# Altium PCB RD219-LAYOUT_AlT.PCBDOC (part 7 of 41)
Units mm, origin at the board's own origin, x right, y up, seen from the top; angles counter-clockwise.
Board outline 209.75 x 159.97 mm, 2 copper layers (TOP, BOTTOM), stack 0 mm thick; 398 components, 199 nets, 1469 pads, 0 vias.
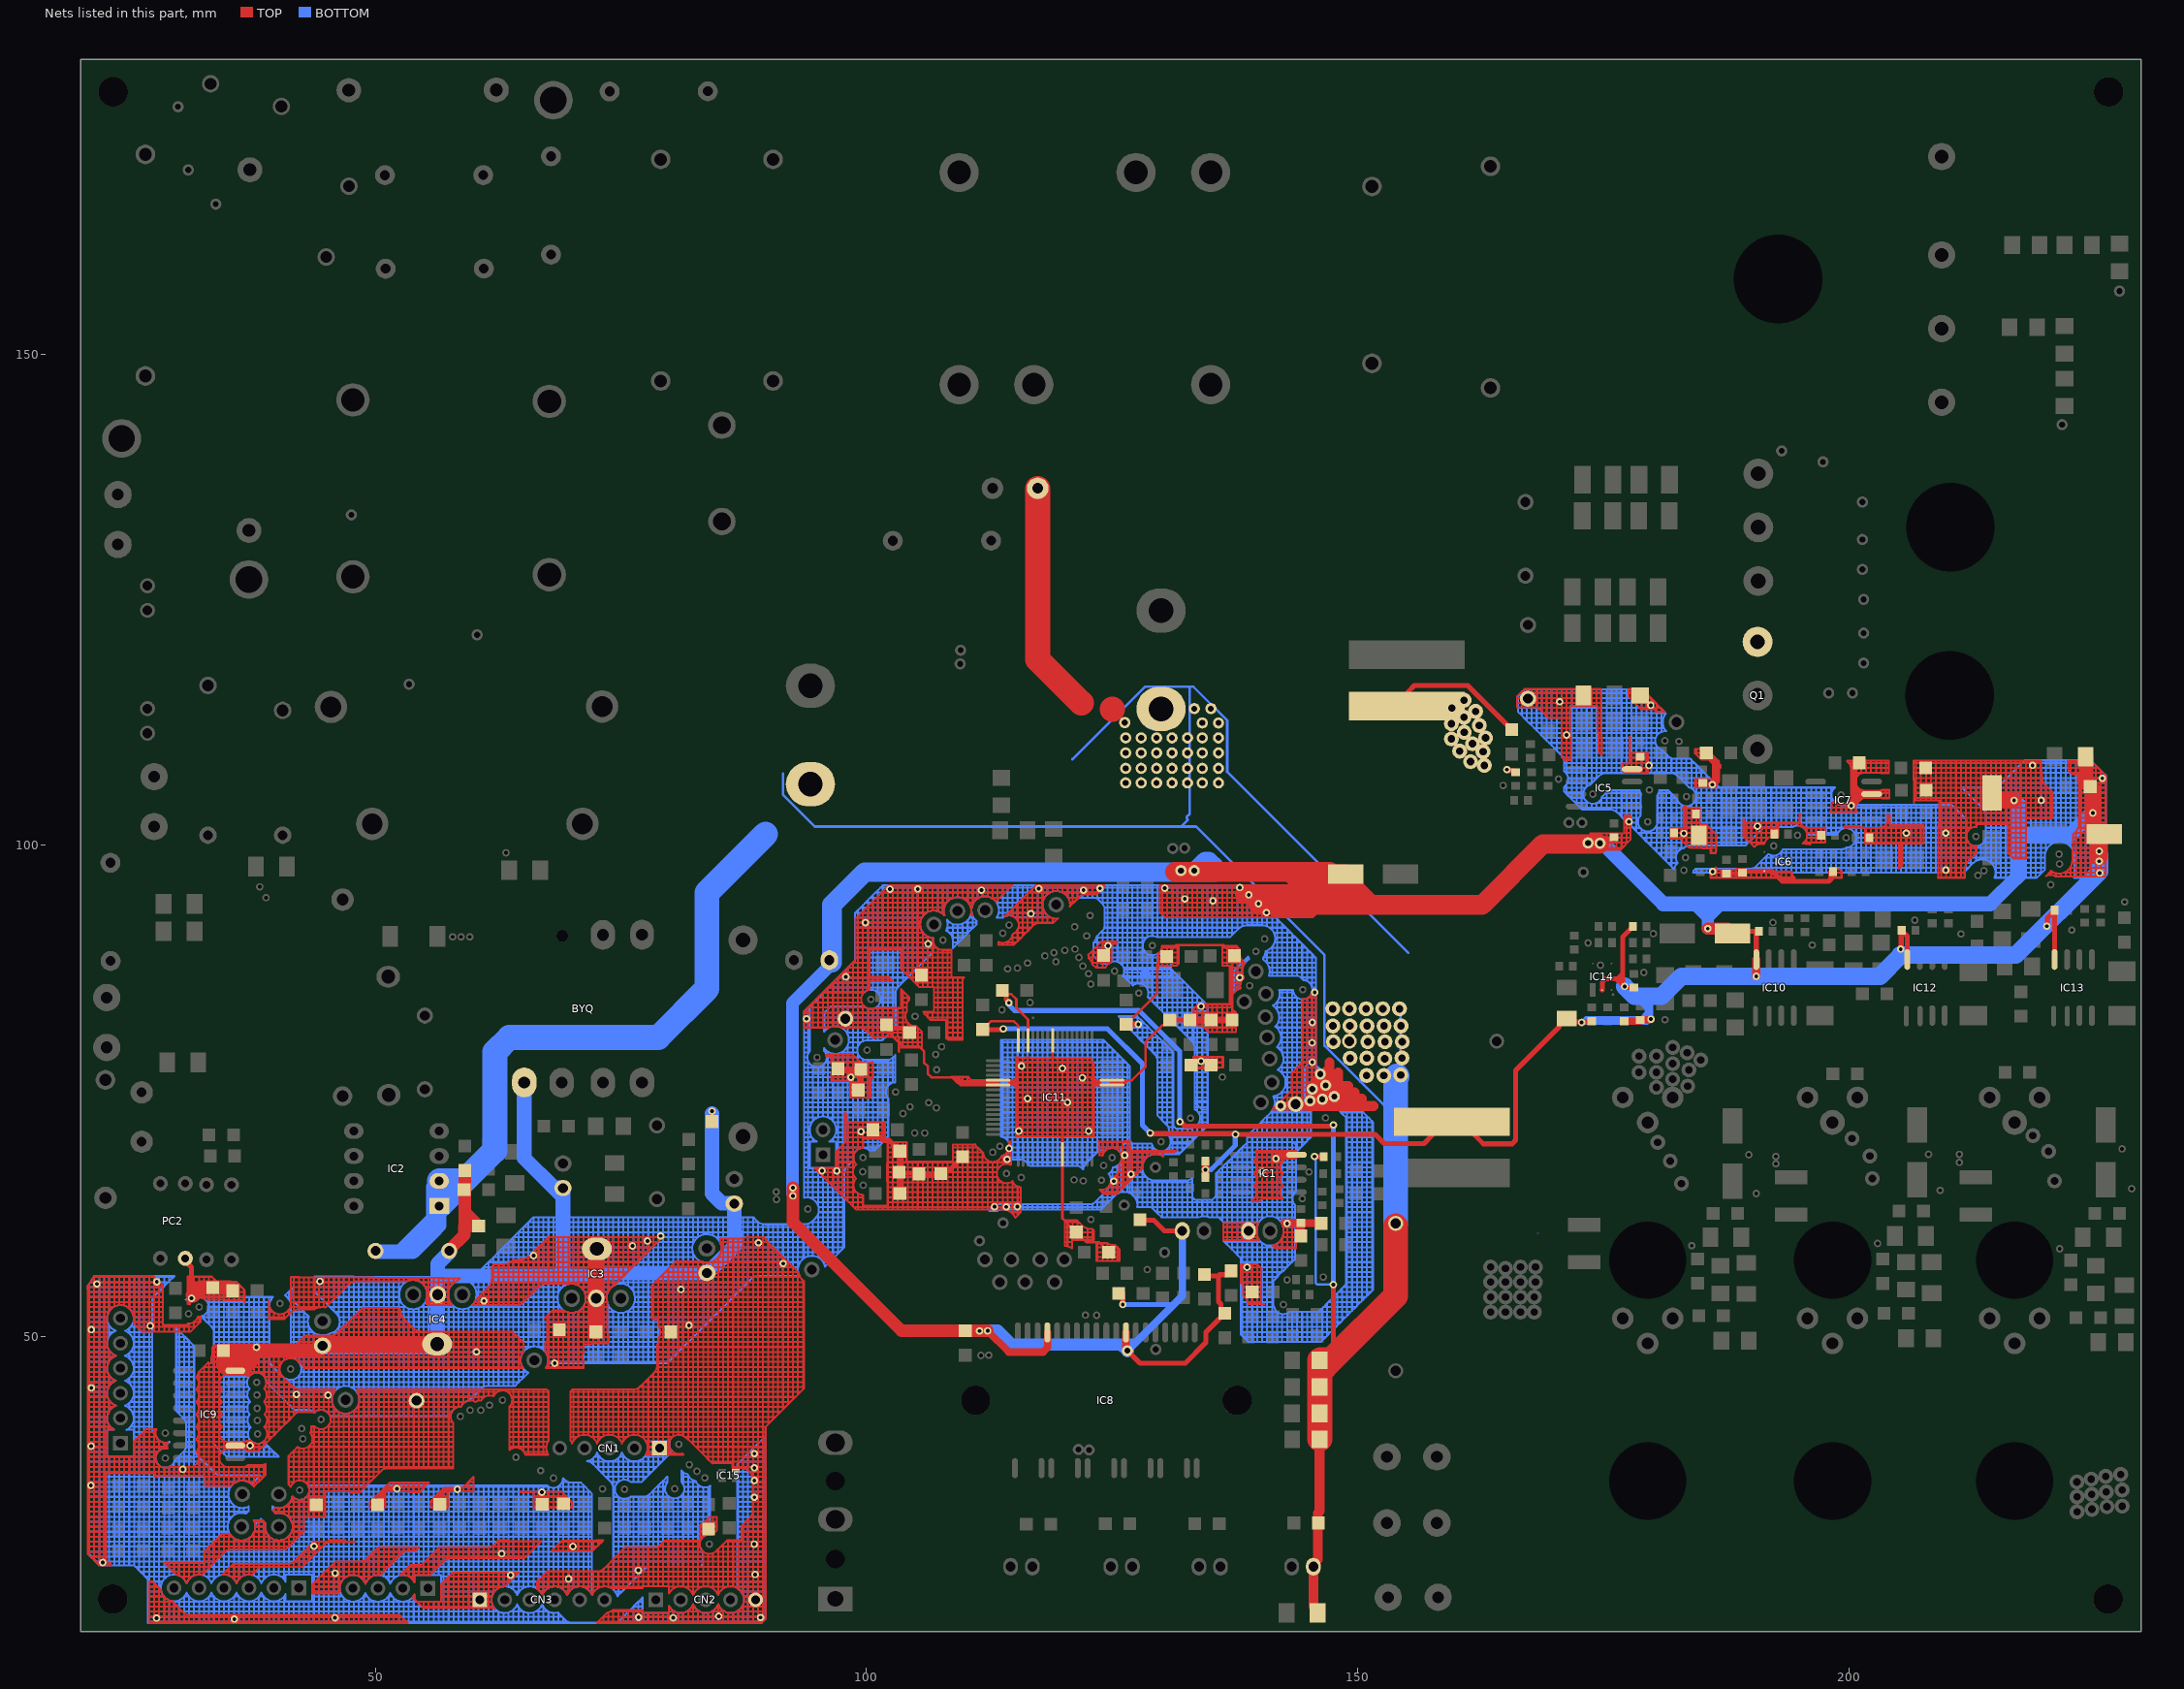
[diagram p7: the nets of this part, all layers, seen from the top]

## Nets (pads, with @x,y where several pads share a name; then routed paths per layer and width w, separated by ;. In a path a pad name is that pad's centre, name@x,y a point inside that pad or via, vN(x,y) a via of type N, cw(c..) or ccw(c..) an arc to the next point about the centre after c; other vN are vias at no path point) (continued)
GND: (continued)
  TOP w0.203: 49.845,46.838 49.845,46.924 ; 49.845,46.838 50.353,46.838 ; 49.845,46.924 49.845,47.432 ; 49.845,46.924 50.353,46.924 ; 49.845,47.432 49.845,47.94 ; 49.845,47.432 50.353,47.432 ; 49.845,47.94 49.845,48.448 ; 49.845,47.94 50.353,47.94 ; 49.845,48.448 49.845,48.956 ; 49.845,48.448 50.353,48.448 ; 49.845,48.956 49.845,49.112 49.845,49.464 ; 49.845,48.956 50.353,48.956 ; 49.845,49.464 49.845,49.972 ; 49.845,49.464 50.353,49.464 ; 49.845,49.972 49.845,50.48 ; 49.845,49.972 50.353,49.972 ; 49.845,50.48 49.845,50.988 ; 49.845,50.48 50.353,50.48 ; 49.845,50.988 49.845,51.496 ; 49.845,50.988 50.353,50.988 ; 49.845,51.496 49.845,52.004 ; 49.845,51.496 50.353,51.496 ; 49.845,52.004 49.845,52.512 ; 49.845,52.004 50.353,52.004 ; 49.845,52.512 49.845,52.938 ; 49.845,52.512 50.353,52.512 ; 49.845,52.938 50.353,52.938 ; 49.845,55.642 49.845,56.009 ; 49.845,55.642 50.353,55.642 ; 49.845,56.009 50.353,56.005 ; 49.859,28.128 50.353,28.128 ; 49.859,28.128 50.274,28.542 50.353,28.542 ; 50.008,35.748 50.353,36.093 ; 50.037,33.716 50.545,34.224 ; 50.037,33.716 50.353,33.716 ; 50.353,20.889 50.353,21.016 ; 50.353,20.889 50.861,20.889 ; 50.353,21.016 50.353,21.524 ; 50.353,21.016 50.861,21.016 ; 50.353,21.524 50.353,21.692 ; 50.353,21.524 50.861,21.524 ; 50.353,21.692 50.861,21.692 ; 50.353,25.746 50.353,26.096 ; 50.353,26.096 50.353,26.604 ; 50.353,26.096 50.847,26.096 ; 50.353,26.604 50.353,27.112 ; 50.353,26.604 50.861,26.604 ; 50.353,27.112 50.353,27.62 ; 50.353,27.112 50.861,27.112 ; 50.353,27.62 50.353,28.128 ; 50.353,27.62 50.861,27.62 ; 50.353,28.128 50.861,28.128 ; 50.353,28.128 50.353,28.542 ; 50.353,28.542 50.861,28.542 ; R74.1@50.353,32.596 R74.1@50.353,32.7 ; R74.1@50.353,32.596 R74.1@50.861,32.596 ; R74.1@50.353,32.7 R74.1@50.861,32.7 ; R74.1@50.353,32.7 50.353,33.03 R74.1@50.353,33.208 ; R74.1@50.353,33.208 50.353,33.716 ; R74.1@50.353,33.208 50.531,33.208 R74.1@50.861,33.208 ; 50.353,33.716 50.564,33.716 50.861,33.716 ; 50.353,36.093 50.353,36.256 ; 50.353,36.093 50.651,36.39 ; 50.353,36.256 50.353,36.764 ; 50.353,36.764 50.353,37.272 ; 50.353,36.764 50.861,36.764 ; 50.353,37.272 50.353,37.78 ; 50.353,37.272 50.861,37.272 ; 50.353,37.78 50.353,38.288 ; 50.353,37.78 50.861,37.78 ; 50.353,38.288 50.353,38.796 ; 50.353,38.288 50.861,38.288 ; 50.353,38.796 50.353,39.304 ; 50.353,38.796 50.861,38.796 ; 50.353,39.304 50.353,39.812 ; 50.353,39.304 50.861,39.304 ; 50.353,39.812 50.353,40.32 ; 50.353,39.812 50.861,39.812 ; 50.353,40.32 50.353,40.828 ; 50.353,40.32 50.861,40.32 ; 50.353,40.828 50.353,41.336 ; 50.353,40.828 50.861,40.828 ; 50.353,41.336 50.353,41.844 ; 50.353,41.336 50.861,41.336 ; 50.353,41.844 50.353,42.352 ; 50.353,41.844 50.861,41.844 ; 50.353,42.352 50.353,42.86 ; 50.353,42.352 50.861,42.352 ; 50.353,42.86 50.353,43.368 ; 50.353,42.86 50.861,42.86 ; 50.353,43.368 50.353,43.876 ; 50.353,43.368 50.861,43.368 ; 50.353,43.876 50.353,44.384 ; 50.353,43.876 50.861,43.876 ; 50.353,44.384 50.353,44.635 ; 50.353,44.384 50.861,44.384 ; 50.353,44.635 50.861,44.635 ; 50.353,46.838 50.353,46.924 ; 50.353,46.838 50.861,46.838 ; 50.353,46.924 50.353,47.432 ; 50.353,46.924 50.861,46.924 ; 50.353,47.432 50.353,47.94 ; 50.353,47.432 50.861,47.432 ; 50.353,47.94 50.353,48.448 ; 50.353,47.94 50.861,47.94 ; 50.353,48.448 50.353,48.956 ; 50.353,48.448 50.861,48.448 ; 50.353,48.956 50.353,49.112 50.353,49.464 ; 50.353,48.956 50.861,48.956 ; 50.353,49.464 50.353,49.972 ; 50.353,49.464 50.861,49.464 ; 50.353,49.972 50.353,50.48 ; 50.353,49.972 50.861,49.972 ; 50.353,50.48 50.353,50.988 ; 50.353,50.48 50.861,50.48 ; 50.353,50.988 50.353,51.496 ; 50.353,50.988 50.861,50.988 ; 50.353,51.496 50.353,52.004 ; 50.353,51.496 50.861,51.496 ; 50.353,52.004 50.353,52.512 ; 50.353,52.004 50.861,52.004 ; 50.353,52.512 50.353,52.938 ; 50.353,52.512 50.861,52.512 ; 50.353,52.938 50.861,52.938 ; 50.353,55.642 50.353,56.005 ; 50.353,55.642 50.861,55.642 ; 50.353,56.005 50.861,56.002 ; 50.545,34.224 50.861,34.54 ; 50.545,34.224 50.861,34.224 ; 50.651,36.39 cw(c51.166,35.875) 50.858,36.535 ; 50.651,36.39 cw(c51.166,35.875) 50.858,36.535 ; 50.847,26.096 50.861,26.11 ; 50.858,36.535 cw(c51.166,35.875) 50.861,36.537 ; 50.858,36.535 cw(c51.166,35.875) 50.861,36.537 ; 50.861,20.889 50.861,21.016 ; 50.861,20.889 51.369,20.889 ; 50.861,21.016 50.861,21.524 ; 50.861,21.016 51.369,21.016 ; 50.861,21.524 50.861,21.692 ; 50.861,21.524 51.369,21.524 ; 50.861,21.692 51.369,21.692 ; 50.861,26.11 50.861,26.604 ; 50.861,26.11 51.355,26.604 ; 50.861,26.604 50.861,27.112 ; 50.861,26.604 51.355,26.604 ; 50.861,27.112 50.861,27.62 ; 50.861,27.112 51.369,27.112 ; 50.861,27.62 50.861,28.128 ; 50.861,27.62 51.369,27.62 ; 50.861,28.128 50.861,28.542 ; 50.861,28.128 51.369,28.128 ; 50.861,28.542 51.369,28.542 ; R74.1@50.861,32.596 R74.1@50.861,32.7 ; R74.1@50.861,32.596 51.006,32.596 51.006,32.7 ; R74.1@50.861,32.7 51.006,32.7 ; R74.1@50.861,32.7 R74.1@50.861,33.208 ; R74.1@50.861,33.208 50.861,33.716 ; R74.1@50.861,33.208 51.006,33.208 ; 50.861,33.716 50.861,34.224 ; 50.861,33.716 51.006,33.716 ; 50.861,34.224 50.861,34.54 ; 50.861,34.224 51.006,34.224 ; 50.861,34.54 51.053,34.732 ; 50.861,36.537 cw(c51.166,35.875) 51.166,36.604 ; 50.861,36.537 cw(c51.166,35.875) 51.166,36.604 ; 50.861,36.537 50.861,36.764 ; 50.861,36.764 51.369,36.764 ; 50.861,36.764 50.861,37.272 ; 50.861,37.272 50.861,37.78 ; 50.861,37.272 51.369,37.272 ; 50.861,37.78 51.369,37.78 ; 50.861,37.78 50.861,38.288 ; 50.861,38.288 50.861,38.796 ; 50.861,38.288 51.369,38.288 ; 50.861,38.796 50.861,39.304 ; 50.861,38.796 51.369,38.796 ; 50.861,39.304 50.861,39.812 ; 50.861,39.304 51.369,39.304 ; 50.861,39.812 50.861,40.32 ; 50.861,39.812 51.369,39.812 ; 50.861,40.32 51.369,40.32 ; 50.861,40.32 50.861,40.828 ; 50.861,40.828 50.861,41.336 ; 50.861,40.828 51.369,40.828 ; 50.861,41.336 51.369,41.336 ; 50.861,41.336 50.861,41.844 ; 50.861,41.844 50.861,42.352 ; 50.861,41.844 51.369,41.844 ; 50.861,42.352 50.861,42.86 ; 50.861,42.352 51.369,42.352 ; 50.861,42.86 50.861,43.368 ; 50.861,42.86 51.369,42.86 ; 50.861,43.368 51.369,43.368 ; 50.861,43.368 50.861,43.876 ; 50.861,43.876 51.369,43.876 ; 50.861,43.876 50.861,44.384 ; 50.861,44.384 51.369,44.384 ; 50.861,44.384 50.861,44.635 ; 50.861,44.635 51.369,44.635 ; 50.861,46.838 50.861,46.924 ; 50.861,46.838 51.369,46.838 ; 50.861,46.924 50.861,47.432 ; 50.861,46.924 51.369,46.924 ; 50.861,47.432 50.861,47.94 ; 50.861,47.432 51.369,47.432 ; 50.861,47.94 50.861,48.448 ; 50.861,47.94 51.369,47.94 ; 50.861,48.448 50.861,48.956 ; 50.861,48.448 51.369,48.448 ; 50.861,48.956 50.861,49.112 50.861,49.464 ; 50.861,48.956 51.369,48.956 ; 50.861,49.464 50.861,49.972 ; 50.861,49.464 51.369,49.464 ; 50.861,49.972 50.861,50.48 ; 50.861,49.972 51.369,49.972 ; 50.861,50.48 50.861,50.988 ; 50.861,50.48 51.369,50.48 ; 50.861,50.988 50.861,51.496 ; 50.861,50.988 51.369,50.988 ; 50.861,51.496 50.861,52.004 ; 50.861,51.496 51.369,51.496 ; 50.861,52.004 50.861,52.512 ; 50.861,52.004 51.369,52.004 ; 50.861,52.512 50.861,52.938 ; 50.861,52.512 51.369,52.512 ; 50.861,52.938 51.369,52.938 ; 50.861,55.642 50.861,56.002 ; 50.861,55.642 51.369,55.642 ; 50.861,56.002 51.369,55.998 ; 51.006,32.7 51.006,33.208 ; 51.006,33.208 51.006,33.716 ; 51.006,33.716 51.006,34.224 ; 51.006,34.224 51.006,34.282 51.369,34.282 ; 51.053,34.732 51.369,34.732 ; 51.053,34.732 51.369,35.048 ; 51.166,36.604 51.369,36.604 ; 51.355,26.604 51.369,26.618 ; 51.369,20.889 51.369,21.016 ; 51.369,20.889 51.877,20.889 ; 51.369,21.016 51.369,21.524 ; 51.369,21.016 51.877,21.016 ; 51.369,21.524 51.369,21.692 ; 51.369,21.524 51.877,21.524 ; 51.369,21.692 51.877,21.692 ; 51.369,26.618 51.863,27.112 ; 51.369,26.618 51.369,27.112 ; 51.369,27.112 51.863,27.112 ; 51.369,27.112 51.369,27.62 ; 51.369,27.62 51.369,28.128 ; 51.369,27.62 51.877,27.62 ; 51.369,28.128 51.877,28.128 ; 51.369,28.128 51.369,28.542 ; 51.369,28.542 51.877,28.542 ; 51.369,34.282 51.369,34.487 51.369,34.732 ; 51.369,34.282 51.877,34.282 ; 51.369,34.732 51.877,34.732 ; 51.369,34.732 51.369,35.048 ; 51.369,35.048 51.468,35.146 51.877,35.146 ; 51.369,36.604 51.369,36.764 ; 51.369,36.604 51.877,36.604 ; 51.369,36.764 51.369,37.272 ; 51.369,36.764 51.877,36.764 ; 51.369,37.272 51.369,37.78 ; 51.369,37.272 51.877,37.272 ; 51.369,37.78 51.369,38.288 ; 51.369,37.78 51.877,37.78 ; 51.369,38.288 51.369,38.796 ; 51.369,38.288 51.877,38.288 ; 51.369,38.796 51.369,39.304 ; 51.369,38.796 51.877,38.796 ; 51.369,39.304 51.369,39.812 ; 51.369,39.304 51.877,39.304 ; 51.369,39.812 51.369,40.32 ; 51.369,39.812 51.877,39.812 ; 51.369,40.32 51.877,40.32 ; 51.369,40.32 51.369,40.828 ; 51.369,40.828 51.369,41.336 ; 51.369,40.828 51.877,40.828 ; 51.369,41.336 51.877,41.336 ; 51.369,41.336 51.369,41.844 ; 51.369,41.844 51.369,42.352 ; 51.369,41.844 51.877,41.844 ; 51.369,42.352 51.369,42.86 ; 51.369,42.352 51.877,42.352 ; 51.369,42.86 51.369,43.368 ; 51.369,42.86 51.877,42.86 ; 51.369,43.368 51.877,43.368 ; 51.369,43.368 51.369,43.876 ; 51.369,43.876 51.877,43.876 ; 51.369,43.876 51.369,44.384 ; 51.369,44.384 51.877,44.384 ; 51.369,44.384 51.369,44.635 ; 51.369,44.635 51.877,44.635 ; 51.369,46.838 51.369,46.924 ; 51.369,46.838 51.877,46.838 ; 51.369,46.924 51.369,47.432 ; 51.369,46.924 51.877,46.924 ; 51.369,47.432 51.369,47.94 ; 51.369,47.432 51.877,47.432 ; 51.369,47.94 51.369,48.448 ; 51.369,47.94 51.877,47.94 ; 51.369,48.448 51.369,48.956 ; 51.369,48.448 51.877,48.448 ; 51.369,48.956 51.369,49.112 51.369,49.464 ; 51.369,48.956 51.877,48.956 ; 51.369,49.464 51.369,49.972 ; 51.369,49.464 51.877,49.464 ; 51.369,49.972 51.369,50.48 ; 51.369,49.972 51.877,49.972 ; 51.369,50.48 51.369,50.988 ; 51.369,50.48 51.877,50.48 ; 51.369,50.988 51.369,51.496 ; 51.369,50.988 51.877,50.988 ; 51.369,51.496 51.369,52.004 ; 51.369,51.496 51.877,51.496 ; 51.369,52.004 51.369,52.512 ; 51.369,52.004 51.877,52.004 ; 51.369,52.512 51.369,52.938 ; 51.369,52.512 51.877,52.512 ; 51.369,52.938 51.877,52.938 ; 51.369,55.642 51.369,55.998 ; 51.369,55.642 51.877,55.642 ; 51.369,55.998 51.877,55.995 ; 51.863,27.112 51.877,27.126 ; 51.877,20.889 52.385,20.889 ; 51.877,20.889 51.877,21.016 ; 51.877,21.016 52.385,21.016 ; 51.877,21.016 51.877,21.524 ; 51.877,21.524 51.877,21.692 ; 51.877,21.524 52.385,21.524 ; 51.877,21.692 52.385,21.692 ; 51.877,27.126 51.877,27.62 ; 51.877,27.126 52.371,27.62 ; 51.877,27.62 52.371,27.62 ; 51.877,27.62 51.877,28.128 ; 51.877,28.128 52.385,28.128 ; 51.877,28.128 51.877,28.542 ; 51.877,28.542 52.385,28.542 ; 51.877,34.282 51.877,34.487 51.877,34.732 ; 51.877,34.282 pad.@52.385,34.282 ; 51.877,34.732 51.877,35.146 ; 51.877,34.732 pad.@52.385,34.732 ; 51.877,35.146 52.385,35.146 ; 51.877,36.604 51.877,36.764 ; 51.877,36.604 52.385,36.604 ; 51.877,36.764 51.877,37.272 ; 51.877,36.764 52.385,36.764 ; 51.877,37.272 51.877,37.78 ; 51.877,37.272 52.385,37.272 ; 51.877,37.78 51.877,38.288 ; 51.877,37.78 52.385,37.78 ; 51.877,38.288 51.877,38.796 ; 51.877,38.288 52.385,38.288 ; 51.877,38.796 51.877,39.304 ; 51.877,38.796 52.385,38.796 ; 51.877,39.304 51.877,39.812 ; 51.877,39.304 52.385,39.304 ; 51.877,39.812 51.877,40.32 ; 51.877,39.812 52.385,39.812 ; 51.877,40.32 51.877,40.828 ; 51.877,40.32 52.385,40.32 ; 51.877,40.828 51.877,41.336 ; 51.877,40.828 52.385,40.828 ; 51.877,41.336 51.877,41.844 ; 51.877,41.336 52.385,41.336 ; 51.877,41.844 51.877,42.352 ; 51.877,41.844 52.385,41.844 ; 51.877,42.352 51.877,42.86 ; 51.877,42.352 52.385,42.352 ; 51.877,42.86 51.877,43.368 ; 51.877,42.86 52.385,42.86 ; 51.877,43.368 51.877,43.876 ; 51.877,43.368 52.385,43.368 ; 51.877,43.876 51.877,44.384 ; 51.877,43.876 52.385,43.876 ; 51.877,44.384 51.877,44.635 ; 51.877,44.384 52.385,44.384 ; 51.877,44.635 52.385,44.635 ; 51.877,46.838 52.385,46.838 ; 51.877,46.838 51.877,46.924 ; 51.877,46.924 52.385,46.924 ; 51.877,46.924 51.877,47.432 ; 51.877,47.432 52.385,47.432 ; 51.877,47.432 51.877,47.94 ; 51.877,47.94 52.385,47.94 ; 51.877,47.94 51.877,48.448 ; 51.877,48.448 52.385,48.448 ; 51.877,48.448 51.877,48.956 ; 51.877,48.956 51.877,49.112 51.877,49.464 ; 51.877,48.956 52.385,48.956 ; 51.877,49.464 52.385,49.464 ; 51.877,49.464 51.877,49.972 ; 51.877,49.972 52.385,49.972 ; 51.877,49.972 51.877,50.48 ; 51.877,50.48 52.385,50.48 ; 51.877,50.48 51.877,50.988 ; 51.877,50.988 52.385,50.988 ; 51.877,50.988 51.877,51.496 ; 51.877,51.496 51.877,52.004 ; 51.877,51.496 52.385,51.496 ; 51.877,52.004 52.385,52.004 ; 51.877,52.004 51.877,52.512 ; 51.877,52.512 51.877,52.938 ; 51.877,52.512 52.385,52.512 ; 51.877,52.938 52.333,52.938 52.385,52.887 ; 51.877,55.642 51.877,55.995 ; 51.877,55.642 52.385,55.642 ; 51.877,55.995 52.385,55.992 ; 52.371,27.62 52.385,27.634 ; 52.385,20.889 52.385,21.016 ; 52.385,20.889 52.893,20.889 ; 52.385,21.016 52.893,21.016 ; 52.385,21.016 52.385,21.524 ; 52.385,21.524 52.385,21.692 ; 52.385,21.524 52.64,21.524 ; 52.385,21.692 52.472,21.692 52.64,21.524 ; 52.385,27.634 52.385,28.128 ; 52.385,27.634 52.759,28.008 ; 52.385,28.128 52.893,28.128 ; 52.385,28.128 52.385,28.542 ; 52.385,28.542 52.893,28.542 ; pad.@52.385,34.282 52.893,34.282 ; pad.@52.385,34.282 pad.@52.385,34.732 ; pad.@52.385,34.732 52.385,35.146 ; pad.@52.385,34.732 52.893,34.732 ; 52.385,35.146 52.893,35.146 ; 52.385,36.604 52.385,36.764 ; 52.385,36.604 52.893,36.604 ; 52.385,36.764 52.385,37.272 ; 52.385,36.764 52.893,36.764 ; 52.385,37.272 52.385,37.78 ; 52.385,37.272 52.893,37.272 ; 52.385,37.78 52.385,38.288 ; 52.385,37.78 52.893,37.78 ; 52.385,38.288 52.385,38.796 ; 52.385,38.288 52.893,38.288 ; 52.385,38.796 52.385,39.304 ; 52.385,38.796 52.893,38.796 ; 52.385,39.304 52.385,39.812 ; 52.385,39.304 52.893,39.304 ; 52.385,39.812 52.385,40.32 ; 52.385,39.812 52.893,39.812 ; 52.385,40.32 52.385,40.828 ; 52.385,40.32 52.893,40.32 ; 52.385,40.828 52.385,41.336 ; 52.385,40.828 52.893,40.828 ; 52.385,41.336 52.385,41.844 ; 52.385,41.336 52.893,41.336 ; 52.385,41.844 52.385,42.352 ; 52.385,41.844 52.893,41.844 ; 52.385,42.352 52.385,42.86 ; 52.385,42.352 52.893,42.352 ; 52.385,42.86 52.385,43.368 ; 52.385,42.86 52.893,42.86 ; 52.385,43.368 52.385,43.876 ; 52.385,43.368 52.893,43.368 ; 52.385,43.876 52.385,44.384 ; 52.385,43.876 52.893,43.876 ; 52.385,44.384 52.385,44.635 ; 52.385,44.384 52.893,44.384 ; 52.385,44.635 52.893,44.635 ; 52.385,46.838 52.385,46.924 ; 52.385,46.838 52.893,46.838 ; 52.385,46.924 52.385,47.432 ; 52.385,46.924 52.893,46.924 ; 52.385,47.432 52.385,47.94 ; 52.385,47.432 52.893,47.432 ; 52.385,47.94 52.385,48.448 ; 52.385,47.94 52.893,47.94 ; 52.385,48.448 52.385,48.956 ; 52.385,48.448 52.893,48.448 ; 52.385,48.956 52.385,49.112 52.385,49.464 ; 52.385,48.956 52.893,48.956 ; 52.385,49.464 52.385,49.972 ; 52.385,49.464 52.893,49.464 ; 52.385,49.972 52.385,50.48 ; 52.385,49.972 52.893,49.972 ; 52.385,50.48 52.385,50.988 ; 52.385,50.48 52.893,50.48 ; 52.385,50.988 52.385,51.496 ; 52.385,50.988 52.893,50.988 ; 52.385,51.496 52.385,52.004 ; 52.385,51.496 52.893,51.496 ; 52.385,52.004 52.385,52.512 ; 52.385,52.004 52.768,52.004 ; 52.385,52.512 52.385,52.887 ; 52.385,52.512 52.561,52.512 ; 52.385,52.887 52.54,52.732 ; 52.385,55.642 52.385,55.992 ; 52.385,55.642 52.893,55.642 ; 52.385,55.992 52.893,55.988 ; 52.54,52.732 ccw(c53.891,52.756) 52.56,52.521 ; 52.54,52.732 ccw(c53.891,52.756) 52.56,52.521 ; 52.56,52.521 ccw(c53.891,52.756) 52.561,52.512 ; 52.56,52.521 ccw(c53.891,52.756) 52.561,52.512 ; 52.561,52.512 ccw(c53.891,52.756) 52.768,52.004 ; 52.561,52.512 ccw(c53.891,52.756) 52.768,52.004 ; 52.64,21.524 52.893,21.271 ; 52.759,28.008 cw(c53.274,27.493) 52.893,28.114 ; 52.759,28.008 cw(c53.274,27.493) 52.893,28.114 ; 52.768,52.004 ccw(c53.891,52.756) 52.893,51.844 ; 52.768,52.004 ccw(c53.891,52.756) 52.893,51.844 ; 52.893,20.889 52.893,21.016 ; 52.893,20.889 53.275,20.889 53.148,21.016 ; 52.893,21.016 52.893,21.271 ; 52.893,21.016 53.148,21.016 ; 52.893,21.271 53.148,21.016 ; 52.893,25.746 cw(c52.809,24.397) 52.903,25.745 cw(c52.809,24.397) 53.401,25.612 ; 52.893,25.746 52.893,26.082 ; 52.893,26.082 52.907,26.096 ; 52.893,28.114 cw(c53.274,27.493) 52.917,28.128 ; 52.893,28.114 cw(c53.274,27.493) 52.917,28.128 ; 52.893,28.114 52.893,28.128 ; 52.893,28.128 52.893,28.542 ; 52.893,28.128 52.917,28.128 ; 52.893,28.542 53.401,28.542 ; 52.893,34.282 53.401,34.282 ; 52.893,34.282 52.893,34.732 ; 52.893,34.732 53.401,34.732 ; 52.893,34.732 52.893,35.146 ; 52.893,35.146 53.401,35.146 ; 52.893,36.604 52.893,36.764 ; 52.893,36.604 53.401,36.604 ; 52.893,36.764 52.893,37.272 ; 52.893,36.764 53.401,36.764 ; 52.893,37.272 52.893,37.78 ; 52.893,37.272 53.401,37.272 ; 52.893,37.78 52.893,38.288 ; 52.893,37.78 53.401,37.78 ; 52.893,38.288 52.893,38.796 ; 52.893,38.288 53.401,38.288 ; 52.893,38.796 52.893,39.304 ; 52.893,38.796 53.401,38.796 ; 52.893,39.304 52.893,39.812 ; 52.893,39.304 53.401,39.304 ; 52.893,39.812 52.893,40.32 ; 52.893,39.812 53.401,39.812 ; 52.893,40.32 52.893,40.828 ; 52.893,40.32 53.401,40.32 ; 52.893,40.828 52.893,41.336 ; 52.893,40.828 53.401,40.828 ; 52.893,41.336 52.893,41.844 ; 52.893,41.336 53.401,41.336 ; 52.893,41.844 52.893,42.352 ; 52.893,41.844 53.401,41.844 ; 52.893,42.352 52.893,42.86 ; 52.893,42.352 53.401,42.352 ; 52.893,42.86 52.893,43.368 ; 52.893,42.86 53.401,42.86 ; 52.893,43.368 52.893,43.876 ; 52.893,43.368 53.401,43.368 ; 52.893,43.876 52.893,44.384 ; 52.893,43.876 53.401,43.876 ; 52.893,44.384 52.893,44.635 ; 52.893,44.384 53.401,44.384 ; 52.893,44.635 53.401,44.635 ; 52.893,46.838 52.893,46.924 ; 52.893,46.838 53.401,46.838 ; 52.893,46.924 52.893,47.432 ; 52.893,46.924 53.401,46.924 ; 52.893,47.432 52.893,47.94 ; 52.893,47.432 53.401,47.432 ; 52.893,47.94 52.893,48.448 ; 52.893,47.94 53.401,47.94 ; 52.893,48.448 52.893,48.956 ; 52.893,48.448 53.401,48.448 ; 52.893,48.956 52.893,49.112 52.893,49.464 ; 52.893,48.956 53.401,48.956 ; 52.893,49.464 52.893,49.972 ; 52.893,49.464 53.401,49.464 ; 52.893,49.972 52.893,50.48 ; 52.893,49.972 53.401,49.972 ; 52.893,50.48 52.893,50.988 ; 52.893,50.48 53.401,50.48 ; 52.893,50.988 52.893,51.496 ; 52.893,50.988 53.401,50.988 ; 52.893,51.496 53.239,51.496 ; 52.893,51.496 52.893,51.844 ; 52.893,51.844 ccw(c53.891,52.756) 52.935,51.8 cw(c53.891,52.756) 52.893,51.844 ; 52.893,55.642 52.893,55.988 ; 52.893,55.988 53.401,55.985 ; 52.907,26.096 53.401,26.59 ; 52.907,26.096 53.401,26.096 ; 52.917,28.128 cw(c53.274,27.493) 53.274,28.222 ; 52.917,28.128 cw(c53.274,27.493) 53.274,28.222 ; 53.239,51.496 53.401,51.334 ; 53.274,28.222 53.401,28.222 ; 53.401,25.612 cw(c52.809,24.397) 53.448,25.588 ; 53.401,25.612 53.401,26.096 ; 53.401,26.096 53.401,26.59 ; 53.401,26.096 53.909,26.096 ; 53.401,26.59 53.415,26.604 ; 53.401,28.222 53.909,28.222 ; 53.401,28.222 53.401,28.542 ; 53.401,28.542 53.909,28.542 ; 53.401,34.282 53.401,34.732 ; 53.401,34.732 53.909,34.732 ; 53.401,34.732 53.401,35.146 ; 53.401,35.146 53.909,35.146 ; 53.401,36.604 53.401,36.764 ; 53.401,36.604 53.909,36.604 ; 53.401,36.764 53.401,37.272 ; 53.401,36.764 53.909,36.764 ; 53.401,37.272 53.401,37.78 ; 53.401,37.272 53.909,37.272 ; 53.401,37.78 53.401,38.288 ; 53.401,37.78 53.909,37.78 ; 53.401,38.288 53.401,38.796 ; 53.401,38.288 53.909,38.288 ; 53.401,38.796 53.401,39.304 ; 53.401,38.796 53.909,38.796 ; 53.401,39.304 53.401,39.812 ; 53.401,39.304 53.909,39.304 ; 53.401,39.812 53.401,40.32 ; 53.401,39.812 53.909,39.812 ; 53.401,40.32 53.401,40.828 ; 53.401,40.32 53.909,40.32 ; 53.401,40.828 53.401,41.336 ; 53.401,40.828 53.909,40.828 ; 53.401,41.336 53.401,41.844 ; 53.401,41.336 53.909,41.336 ; 53.401,41.844 53.401,42.352 ; 53.401,41.844 53.909,41.844 ; 53.401,42.352 53.401,42.86 ; 53.401,42.352 53.909,42.352 ; 53.401,42.86 53.401,43.368 ; 53.401,42.86 TP30.1@53.909,42.86 ; 53.401,43.368 TP30.1@53.909,43.368 ; 53.401,43.368 53.401,43.876 ; 53.401,43.876 53.401,44.384 ; 53.401,43.876 TP30.1@53.909,43.876 ; 53.401,44.384 53.401,44.635 ; 53.401,44.384 53.909,44.384 ; 53.401,44.635 53.909,44.635 ; 53.401,46.838 53.909,46.838 ; 53.401,46.838 53.401,46.924 ; 53.401,46.924 53.909,46.924 ; 53.401,46.924 53.401,47.432 ; 53.401,47.432 53.909,47.432 ; 53.401,47.432 53.401,47.94 ; 53.401,47.94 53.909,47.94 ; 53.401,47.94 53.401,48.448 ; 53.401,48.448 53.909,48.448 ; 53.401,48.448 53.401,48.956 ; 53.401,48.956 53.909,48.956 ; 53.401,48.956 53.401,49.112 53.401,49.464 ; 53.401,49.464 53.909,49.464 ; 53.401,49.464 53.401,49.972 ; 53.401,49.972 53.909,49.972 ; 53.401,49.972 53.401,50.48 ; 53.401,50.48 53.909,50.48 ; 53.401,50.48 53.401,50.988 ; 53.401,50.988 53.401,51.334 ; 53.401,50.988 53.747,50.988 ; 53.401,51.334 53.747,50.988 ; 53.401,55.704 cw(c53.862,54.354) 53.909,55.78 ; 53.401,55.704 53.401,55.985 ; 53.401,55.985 53.909,55.982 ; 53.415,26.604 53.909,26.604 ; 53.415,26.604 53.576,26.764 53.909,26.764 ; 53.448,25.588 cw(c52.809,24.397) 53.909,25.182 ; 53.448,25.588 53.909,25.588 ; 53.867,23.556 ccw(c52.809,24.397) 53.909,23.612 ; 53.867,23.556 53.909,23.556 ; 53.909,23.556 53.997,23.556 ; 53.909,23.556 53.909,23.612 ; 53.909,25.182 cw(c52.809,24.397) 53.997,25.041 ; 53.909,25.182 53.909,25.588 ; 53.909,25.588 53.997,25.588 ; 53.909,25.588 53.909,26.096 ; 53.909,26.096 53.909,26.604 ; 53.909,26.096 54.417,26.096 ; 53.909,26.604 53.909,26.764 ; 53.909,26.604 54.417,26.604 ; 53.909,26.764 54.417,26.764 ; 53.909,28.222 54.115,28.222 54.436,28.542 53.909,28.542 ; 53.909,28.222 53.909,28.542 ; 53.909,34.206 54.417,34.206 ; 53.909,34.206 53.909,34.224 ; 53.909,34.224 54.417,34.224 ; 53.909,34.224 53.909,34.732 ; 53.909,34.732 54.417,34.732 ; 53.909,34.732 53.909,35.146 ; 53.909,35.146 54.417,35.146 ; 53.909,36.604 53.909,36.764 ; 53.909,36.604 54.417,36.604 ; 53.909,36.764 53.909,37.272 ; 53.909,36.764 54.417,36.764 ; 53.909,37.272 53.909,37.78 ; 53.909,37.272 54.417,37.272 ; 53.909,37.78 53.909,38.288 ; 53.909,37.78 54.417,37.78 ; 53.909,38.288 53.909,38.796 ; 53.909,38.288 54.417,38.288 ; 53.909,38.796 53.909,39.304 ; 53.909,38.796 54.417,38.796 ; 53.909,39.304 53.909,39.812 ; 53.909,39.304 54.417,39.304 ; 53.909,39.812 53.909,40.32 ; 53.909,39.812 54.417,39.812 ; 53.909,40.32 53.909,40.828 ; 53.909,40.32 54.417,40.32 ; 53.909,40.828 53.909,41.336 ; 53.909,40.828 54.417,40.828 ; 53.909,41.336 53.909,41.844 ; 53.909,41.336 54.417,41.336 ; 53.909,41.844 53.909,42.352 ; 53.909,41.844 54.417,41.844 ; 53.909,42.352 TP30.1@53.909,42.86 ; 53.909,42.352 54.417,42.352 ; TP30.1@53.909,42.86 TP30.1@53.909,43.368 ; TP30.1@53.909,42.86 TP30.1@54.417,42.86 ; TP30.1@53.909,43.368 TP30.1@54.417,43.368 ; TP30.1@53.909,43.368 TP30.1@53.909,43.876 ; TP30.1@53.909,43.876 53.909,44.384 ; TP30.1@53.909,43.876 TP30.1@54.417,43.876 ; 53.909,44.384 53.909,44.635 ; 53.909,44.384 54.417,44.384 ; 53.909,44.635 54.417,44.635 ; 53.909,46.838 53.909,46.924 ; 53.909,46.838 54.417,46.838 ; 53.909,46.924 53.909,47.432 ; 53.909,46.924 54.417,46.924 ; 53.909,47.432 53.909,47.94 ; 53.909,47.432 54.417,47.432 ; 53.909,47.94 53.909,48.448 ; 53.909,47.94 54.417,47.94 ; 53.909,48.448 53.909,48.956 ; 53.909,48.448 54.417,48.448 ; 53.909,48.956 53.909,49.112 53.909,49.464 ; 53.909,48.956 54.417,48.956 ; 53.909,49.464 53.909,49.972 ; 53.909,49.464 54.417,49.464 ; 53.909,49.972 53.909,50.48 ; 53.909,49.972 54.417,49.972 ; 53.909,50.48 54.417,50.48 ; 53.909,50.48 53.909,50.835 ; 53.909,50.835 cw(c54.77,51.877) 53.814,50.921 ccw(c54.77,51.877) 53.909,50.835 ; 53.909,50.835 ccw(c54.77,51.877) 54.417,50.572 ; 53.909,50.835 ccw(c54.77,51.877) 54.417,50.572 ; 53.909,55.78 cw(c53.862,54.354) 53.912,55.78 cw(c53.862,54.354) 54.417,55.668 ; 53.909,55.78 53.909,55.982 ; 53.909,55.982 54.417,55.978 ; 53.997,23.283 53.997,23.556 ; 53.997,23.283 54.235,23.045 ; 53.997,25.041 53.997,25.588 ; 53.997,25.588 53.997,25.749 54.417,25.749 ; 54.235,23.045 54.417,23.045 ; 54.235,23.045 54.74,22.54 ; 54.417,23.045 54.925,23.045 ; 54.417,25.749 54.925,25.749 ; 54.417,25.749 54.417,26.096 ; 54.417,26.096 54.417,26.604 ; 54.417,26.096 54.925,26.096 ; 54.417,26.604 54.925,26.604 ; 54.417,26.604 54.417,26.764 ; 54.417,26.764 ccw(c54.417,27.493) 54.925,26.971 ; 54.417,26.764 ccw(c54.417,27.493) 54.925,26.971 ; 54.417,34.206 54.417,34.224 ; 54.417,34.206 54.511,34.206 54.53,34.224 ; 54.417,34.224 54.417,34.732 ; 54.417,34.224 54.53,34.224 ; 54.417,34.732 54.925,34.732 ; 54.417,34.732 54.417,35.146 ; 54.417,35.146 54.925,35.146 ; 54.417,36.604 54.417,36.764 ; 54.417,36.604 54.925,36.604 ; 54.417,36.764 54.417,37.272 ; 54.417,36.764 54.925,36.764 ; 54.417,37.272 54.417,37.78 ; 54.417,37.272 54.925,37.272 ; 54.417,37.78 54.417,38.288 ; 54.417,37.78 54.925,37.78 ; 54.417,38.288 54.417,38.796 ; 54.417,38.288 54.925,38.288 ; 54.417,38.796 54.417,39.304 ; 54.417,38.796 54.925,38.796 ; 54.417,39.304 54.417,39.812 ; 54.417,39.304 54.925,39.304 ; 54.417,39.812 54.417,40.32 ; 54.417,39.812 54.925,39.812 ; 54.417,40.32 54.417,40.828 ; 54.417,40.32 54.925,40.32 ; 54.417,40.828 54.417,41.336 ; 54.417,40.828 54.925,40.828 ; 54.417,41.336 54.417,41.844 ; 54.417,41.336 54.925,41.336 ; 54.417,41.844 54.417,42.352 ; 54.417,41.844 54.925,41.844 ; 54.417,42.352 TP30.1@54.417,42.86 ; 54.417,42.352 54.925,42.352 ; TP30.1@54.417,42.86 TP30.1@54.417,43.368 ; TP30.1@54.417,42.86 54.925,42.86 ; TP30.1@54.417,43.368 TP30.1@54.925,43.368 ; TP30.1@54.417,43.368 TP30.1@54.417,43.876 ; TP30.1@54.417,43.876 54.417,44.384 ; TP30.1@54.417,43.876 54.925,43.876 ; 54.417,44.384 54.417,44.635 ; 54.417,44.384 54.925,44.384 ; 54.417,44.635 54.925,44.635 ; 54.417,46.838 54.925,46.838 ; 54.417,46.838 54.417,46.924 ; 54.417,46.924 54.925,46.924 ; 54.417,46.924 54.417,47.432 ; 54.417,47.432 54.925,47.432 ; 54.417,47.432 54.417,47.94 ; 54.417,47.94 54.925,47.94 ; 54.417,47.94 54.417,48.448 ; 54.417,48.448 54.925,48.448 ; 54.417,48.448 54.417,48.956 ; 54.417,48.956 IC4.4@54.925,48.956 ; 54.417,48.956 54.417,49.112 54.417,49.464 ; 54.417,49.464 IC4.4@54.925,49.464 ; 54.417,49.464 54.417,49.972 ; 54.417,49.972 54.925,49.972 ; 54.417,49.972 54.417,50.48 ; 54.417,50.48 54.925,50.48 ; 54.417,50.48 54.417,50.572 ; 54.417,50.572 ccw(c54.77,51.877) 54.42,50.571 ; 54.417,50.572 ccw(c54.77,51.877) 54.42,50.571 ; 54.417,55.668 cw(c53.862,54.354) 54.42,55.667 cw(c53.862,54.354) 54.618,55.564 cw(c53.862,54.354) 54.624,55.56 ; 54.417,55.668 54.417,55.978 ; 54.417,55.978 54.925,55.975 ; 54.42,50.571 ccw(c54.77,51.877) 54.77,50.525 ; 54.42,50.571 ccw(c54.77,51.877) 54.77,50.525 ; 54.53,34.224 54.925,34.619 ; 54.624,55.56 cw(c53.862,54.354) 54.923,55.308 cw(c53.862,54.354) 54.925,55.306 ; 54.624,55.56 54.925,55.56 ; 54.74,22.54 54.925,22.54 ; 54.74,22.54 54.908,22.372 54.925,22.372 ; 54.77,50.525 54.925,50.525 ; 54.925,22.372 54.925,22.54 ; 54.925,22.372 55.433,22.372 ; 54.925,22.54 55.433,22.54 ; 54.925,22.54 54.925,23.045 ; 54.925,23.045 55.433,23.045 ; 54.925,25.749 55.433,25.749 ; 54.925,25.749 54.925,26.096 ; 54.925,26.096 54.925,26.604 ; 54.925,26.096 55.433,26.096 ; 54.925,26.604 55.433,26.604 ; 54.925,26.604 54.925,26.971 ; 54.925,26.971 ccw(c54.417,27.493) 54.932,26.978 ; 54.925,26.971 ccw(c54.417,27.493) 54.932,26.978 ; 54.925,34.619 55.038,34.732 ; 54.925,34.619 54.925,34.732 ; 54.925,34.732 55.038,34.732 ; 54.925,34.732 54.925,35.146 ; 54.925,35.146 55.452,35.146 55.038,34.732 ; 54.925,36.604 54.925,36.764 ; 54.925,36.604 55.433,36.604 ; 54.925,36.764 54.925,37.272 ; 54.925,36.764 55.433,36.764 ; 54.925,37.272 54.925,37.78 ; 54.925,37.272 55.433,37.272 ; 54.925,37.78 54.925,38.288 ; 54.925,37.78 55.433,37.78 ; 54.925,38.288 54.925,38.796 ; 54.925,38.288 55.433,38.288 ; 54.925,38.796 54.925,39.304 ; 54.925,38.796 55.433,38.796 ; 54.925,39.304 54.925,39.812 ; 54.925,39.304 55.433,39.304 ; 54.925,39.812 54.925,40.32 ; 54.925,39.812 55.433,39.812 ; 54.925,40.32 54.925,40.828 ; 54.925,40.32 55.433,40.32 ; 54.925,40.828 54.925,41.336 ; 54.925,40.828 55.433,40.828 ; 54.925,41.336 54.925,41.844 ; 54.925,41.336 55.433,41.336 ; 54.925,41.844 54.925,42.352 ; 54.925,41.844 55.433,41.844 ; 54.925,42.352 54.925,42.86 ; 54.925,42.352 55.433,42.352 ; 54.925,42.86 TP30.1@54.925,43.368 ; 54.925,42.86 55.433,42.86 ; TP30.1@54.925,43.368 55.433,43.368 ; TP30.1@54.925,43.368 54.925,43.876 ; 54.925,43.876 54.925,44.384 ; 54.925,43.876 55.433,43.876 ; 54.925,44.384 54.925,44.635 ; 54.925,44.384 55.433,44.384 ; 54.925,44.635 55.433,44.635 ; 54.925,46.838 54.925,46.924 ; 54.925,46.838 55.433,46.838 ; 54.925,46.924 54.925,47.432 ; 54.925,46.924 55.433,46.924 ; 54.925,47.432 54.925,47.94 ; 54.925,47.432 55.433,47.432 ; 54.925,47.94 54.925,48.448 ; 54.925,47.94 55.433,47.94 ; 54.925,48.448 IC4.4@54.925,48.956 ; 54.925,48.448 IC4.4@55.433,48.448 ; IC4.4@54.925,48.956 54.925,49.112 IC4.4@54.925,49.464 ; IC4.4@54.925,48.956 IC4.4@55.433,48.956 ; IC4.4@54.925,49.464 54.925,49.972 ; IC4.4@54.925,49.464 IC4.4@55.433,49.464 ; 54.925,49.972 54.925,50.48 ; 54.925,49.972 IC4.4@55.433,49.972 ; 54.925,50.48 54.925,50.525 ; 54.925,50.48 55.433,50.48 ; 54.925,50.525 55.433,50.525 ; 54.925,55.306 cw(c53.862,54.354) 55.107,55.052 ; 54.925,55.306 54.925,55.56 ; 54.925,55.56 54.925,55.975 ; 54.925,55.56 55.433,55.56 ; 54.925,55.975 55.433,55.971 ; 54.932,26.978 55.066,27.112 ; 55.066,27.112 55.433,27.479 ; 55.066,27.112 55.433,27.112 ; 55.107,55.052 cw(c53.862,54.354) 55.11,55.045 cw(c53.862,54.354) 55.276,54.544 ; 55.107,55.052 55.433,55.052 ; 55.243,53.528 55.433,53.528 ; 55.243,53.528 55.243,53.316 55.329,53.229 55.433,53.229 ; 55.243,53.528 55.243,53.865 ; 55.243,53.865 ccw(c53.862,54.227) 55.276,54.036 ; 55.276,54.036 ccw(c53.862,54.227) 55.289,54.227 55.289,54.354 ccw(c53.862,54.354) 55.276,54.544 ; 55.276,54.036 55.433,54.036 ; 55.276,54.544 55.433,54.544 ; 55.433,22.372 55.433,22.54 ; 55.433,22.372 55.941,22.372 ; 55.433,22.54 55.433,23.045 ; 55.433,22.54 55.941,22.54 ; 55.433,23.045 55.941,23.045 ; 55.433,25.749 55.579,25.749 55.927,26.096 ; 55.433,25.749 55.433,26.096 ; 55.433,26.096 55.433,26.604 ; 55.433,26.096 55.927,26.096 ; 55.433,26.604 55.433,27.112 ; 55.433,26.604 55.941,26.604 ; 55.433,27.112 55.433,27.479 ; 55.433,27.112 55.941,27.112 ; 55.433,27.479 55.574,27.62 ; 55.433,36.604 55.433,36.764 ; 55.433,36.604 55.941,36.604 ; 55.433,36.764 55.433,37.272 ; 55.433,36.764 55.941,36.764 ; 55.433,37.272 55.433,37.78 ; 55.433,37.272 55.941,37.272 ; 55.433,37.78 55.433,38.288 ; 55.433,37.78 55.941,37.78 ; 55.433,38.288 55.433,38.796 ; 55.433,38.288 55.941,38.288 ; 55.433,38.796 55.433,39.304 ; 55.433,38.796 55.941,38.796 ; 55.433,39.304 55.433,39.812 ; 55.433,39.304 55.941,39.304 ; 55.433,39.812 55.433,40.32 ; 55.433,39.812 55.941,39.812 ; 55.433,40.32 55.433,40.828 ; 55.433,40.32 55.941,40.32 ; 55.433,40.828 55.433,41.336 ; 55.433,40.828 55.941,40.828 ; 55.433,41.336 55.433,41.844 ; 55.433,41.336 55.941,41.336 ; 55.433,41.844 55.433,42.352 ; 55.433,41.844 55.941,41.844 ; 55.433,42.352 55.433,42.86 ; 55.433,42.352 55.941,42.352 ; 55.433,42.86 55.433,43.368 ; 55.433,42.86 55.941,42.86 ; 55.433,43.368 55.433,43.876 ; 55.433,43.368 55.941,43.368 ; 55.433,43.876 55.433,44.384 ; 55.433,43.876 55.941,43.876 ; 55.433,44.384 55.433,44.635 ; 55.433,44.384 55.941,44.384 ; 55.433,44.635 55.941,44.635 ; 55.433,46.838 55.433,46.924 ; 55.433,46.838 55.941,46.838 ; 55.433,46.924 55.433,47.432 ; 55.433,46.924 55.941,46.924 ; 55.433,47.432 55.433,47.94 ; 55.433,47.432 55.941,47.432 ; 55.433,47.94 IC4.4@55.433,48.448 ; 55.433,47.94 55.941,47.94 ; IC4.4@55.433,48.448 IC4.4@55.433,48.956 ; IC4.4@55.433,48.448 IC4.4@55.941,48.448 ; IC4.4@55.433,48.956 55.433,49.112 IC4.4@55.433,49.464 ; IC4.4@55.433,48.956 IC4.4@55.941,48.956 ; IC4.4@55.433,49.464 IC4.4@55.433,49.972 ; IC4.4@55.433,49.464 IC4.4@55.941,49.464 ; IC4.4@55.433,49.972 55.433,50.48 ; IC4.4@55.433,49.972 IC4.4@55.941,49.972 ; 55.433,50.48 55.433,50.525 ; 55.433,50.48 55.941,50.48 ; 55.433,50.525 55.941,50.525 ; 55.433,53.229 55.941,53.229 ; 55.433,53.229 55.433,53.528 ; 55.433,53.528 55.433,54.036 ; 55.433,53.528 IC4.2@55.941,53.528 ; 55.433,54.036 55.433,54.544 ; 55.433,54.036 IC4.2@55.941,54.036 ; 55.433,54.544 55.433,55.052 ; 55.433,54.544 IC4.2@55.941,54.544 ; 55.433,55.052 55.433,55.56 ; 55.433,55.052 IC4.2@55.941,55.052 ; 55.433,55.56 55.433,55.971 ; 55.433,55.56 55.941,55.56 ; 55.433,55.971 55.941,55.968 ; 55.574,27.62 55.941,27.987 ; 55.574,27.62 55.941,27.62 ; 55.669,32.7 R76.1@55.941,32.7 ; 55.669,32.7 55.669,33.208 ; 55.669,32.7 55.669,32.596 R76.1@55.941,32.596 ; 55.669,33.208 R76.1@55.941,33.208 ; 55.669,33.208 55.669,33.302 R76.1@55.941,33.575 ; 55.927,26.096 55.941,26.11 ; 55.941,22.372 55.941,22.54 ; 55.941,22.372 56.449,22.372 ; 55.941,22.54 55.941,23.045 ; 55.941,22.54 56.449,22.54 ; 55.941,23.045 56.449,23.045 ; 55.941,26.11 56.435,26.604 ; 55.941,26.11 55.941,26.604 ; 55.941,26.604 56.435,26.604 ; 55.941,26.604 55.941,27.112 ; 55.941,27.112 56.449,27.112 ; 55.941,27.112 55.941,27.62 ; 55.941,27.62 56.449,27.62 ; 55.941,27.62 55.941,27.987 ; 55.941,27.987 56.082,28.128 ; R76.1@55.941,32.596 R76.1@56.449,32.596 ; R76.1@55.941,32.596 R76.1@55.941,32.7 ; R76.1@55.941,32.7 R76.1@56.449,32.7 ; R76.1@55.941,32.7 R76.1@55.941,33.208 ; R76.1@55.941,33.208 R76.1@56.449,33.208 ; R76.1@55.941,33.208 R76.1@55.941,33.575 ; R76.1@55.941,33.575 56.082,33.716 ; 55.941,36.604 55.941,36.764 ; 55.941,36.604 56.449,36.604 ; 55.941,36.764 55.941,37.272 ; 55.941,36.764 56.449,36.764 ; 55.941,37.272 55.941,37.78 ; 55.941,37.272 56.449,37.272 ; 55.941,37.78 55.941,38.288 ; 55.941,37.78 56.449,37.78 ; 55.941,38.288 55.941,38.796 ; 55.941,38.288 56.449,38.288 ; 55.941,38.796 55.941,39.304 ; 55.941,38.796 56.449,38.796 ; 55.941,39.304 55.941,39.812 ; 55.941,39.304 56.449,39.304 ; 55.941,39.812 55.941,40.32 ; 55.941,39.812 56.449,39.812 ; 55.941,40.32 55.941,40.828 ; 55.941,40.32 56.449,40.32 ; 55.941,40.828 55.941,41.336 ; 55.941,40.828 56.449,40.828 ; 55.941,41.336 55.941,41.844 ; 55.941,41.336 56.449,41.336 ; 55.941,41.844 55.941,42.352 ; 55.941,41.844 56.449,41.844 ; 55.941,42.352 55.941,42.86 ; 55.941,42.352 56.449,42.352 ; 55.941,42.86 55.941,43.368 ; 55.941,42.86 56.449,42.86 ; 55.941,43.368 55.941,43.876 ; 55.941,43.368 56.449,43.368 ; 55.941,43.876 55.941,44.384 ; 55.941,43.876 56.449,43.876 ; 55.941,44.384 55.941,44.635 ; 55.941,44.384 56.449,44.384 ; 55.941,44.635 56.449,44.635 ; 55.941,46.838 55.941,46.924 ; 55.941,46.838 56.449,46.838 ; 55.941,46.924 55.941,47.432 ; 55.941,46.924 56.449,46.924 ; 55.941,47.432 55.941,47.94 ; 55.941,47.432 56.449,47.432 ; 55.941,47.94 IC4.4@55.941,48.448 ; 55.941,47.94 56.449,47.94 ; IC4.4@55.941,48.448 IC4.4@55.941,48.956 ; IC4.4@55.941,48.448 IC4.4@56.449,48.448 ; IC4.4@55.941,48.956 55.941,49.112 IC4.4@55.941,49.464 ; IC4.4@55.941,48.956 IC4.4@56.449,48.956 ; IC4.4@55.941,49.464 IC4.4@55.941,49.972 ; IC4.4@55.941,49.464 IC4.4@56.449,49.464 ; IC4.4@55.941,49.972 55.941,50.48 ; IC4.4@55.941,49.972 IC4.4@56.449,49.972 ; 55.941,50.48 55.941,50.525 ; 55.941,50.48 56.449,50.48 ; 55.941,50.525 56.449,50.525 ; 55.941,53.229 IC4.2@55.941,53.528 ; 55.941,53.229 56.449,53.229 ; IC4.2@55.941,53.528 IC4.2@55.941,54.036 ; IC4.2@55.941,53.528 IC4.2@56.449,53.528 ; IC4.2@55.941,54.036 IC4.2@55.941,54.544 ; IC4.2@55.941,54.036 IC4.2@56.449,54.036 ; IC4.2@55.941,54.544 IC4.2@55.941,55.052 ; IC4.2@55.941,54.544 IC4.2@56.449,54.544 ; IC4.2@55.941,55.052 55.941,55.56 ; IC4.2@55.941,55.052 IC4.2@56.449,55.052 ; 55.941,55.56 55.941,55.968 ; 55.941,55.56 56.449,55.56 ; 55.941,55.968 56.449,55.965 ; 56.082,28.128 56.449,28.495 ; 56.082,28.128 56.449,28.128 ; 56.082,33.716 56.449,34.083 ; 56.082,33.716 56.449,33.716 ; 56.435,26.604 56.449,26.618 ; 56.449,22.372 56.449,22.54 ; 56.449,22.372 56.957,22.372 ; 56.449,22.54 56.449,23.045 ; 56.449,22.54 56.957,22.54 ; 56.449,23.045 56.7,23.045 56.7,23.048 ; 56.449,26.618 56.943,27.112 ; 56.449,26.618 56.449,27.112 ; 56.449,27.112 56.943,27.112 ; 56.449,27.112 56.449,27.62 ; 56.449,27.62 56.957,27.62 ; 56.449,27.62 56.449,28.128 ; 56.449,28.128 56.449,28.495 ; 56.449,28.128 56.957,28.128 ; 56.449,28.495 56.497,28.542 56.957,28.542 ; R76.1@56.449,32.596 R76.1@56.449,32.7 ; R76.1@56.449,32.596 R76.1@56.957,32.596 ; R76.1@56.449,32.7 R76.1@56.449,33.208 ; R76.1@56.449,32.7 R76.1@56.957,32.7 ; R76.1@56.449,33.208 56.449,33.716 ; R76.1@56.449,33.208 56.786,33.208 R76.1@56.957,33.208 ; 56.449,33.716 56.786,33.716 56.957,33.716 ; 56.449,33.716 56.449,34.083 ; 56.449,34.083 56.59,34.224 ; 56.449,36.604 56.449,36.764 ; 56.449,36.604 56.957,36.604 ; 56.449,36.764 56.449,37.272 ; 56.449,36.764 56.957,36.764 ; 56.449,37.272 56.449,37.78 ; 56.449,37.272 56.957,37.272 ; 56.449,37.78 56.449,38.288 ; 56.449,37.78 56.957,37.78 ; 56.449,38.288 56.449,38.796 ; 56.449,38.288 56.957,38.288 ; 56.449,38.796 56.449,39.304 ; 56.449,38.796 56.957,38.796 ; 56.449,39.304 56.449,39.812 ; 56.449,39.304 56.957,39.304 ; 56.449,39.812 56.449,40.32 ; 56.449,39.812 56.957,39.812 ; 56.449,40.32 56.449,40.828 ; 56.449,40.32 56.957,40.32 ; 56.449,40.828 56.449,41.336 ; 56.449,40.828 56.957,40.828 ; 56.449,41.336 56.449,41.844 ; 56.449,41.336 56.957,41.336 ; 56.449,41.844 56.449,42.352 ; 56.449,41.844 56.957,41.844 ; 56.449,42.352 56.449,42.86 ; 56.449,42.352 56.957,42.352 ; 56.449,42.86 56.449,43.368 ; 56.449,42.86 56.957,42.86 ; 56.449,43.368 56.449,43.876 ; 56.449,43.368 56.957,43.368 ; 56.449,43.876 56.449,44.384 ; 56.449,43.876 56.957,43.876 ; 56.449,44.384 56.449,44.635 ; 56.449,44.384 56.957,44.384 ; 56.449,44.635 56.957,44.635 ; 56.449,46.838 56.449,46.924 ; 56.449,46.838 56.957,46.838 ; 56.449,46.924 56.449,47.432 ; 56.449,46.924 56.957,46.924 ; 56.449,47.432 56.449,47.94 ; 56.449,47.432 56.957,47.432 ; 56.449,47.94 IC4.4@56.449,48.448 ; 56.449,47.94 56.957,47.94 ; IC4.4@56.449,48.448 IC4.4@56.449,48.956 ; IC4.4@56.449,48.448 IC4.4@56.957,48.448 ; IC4.4@56.449,48.956 IC4.4@56.957,48.956 ; IC4.4@56.449,48.956 IC4.4@56.449,49.464 ; IC4.4@56.449,49.464 IC4.4@56.449,49.972 ; IC4.4@56.449,49.464 IC4.4@56.957,49.464 ; IC4.4@56.449,49.972 56.449,50.48 ; IC4.4@56.449,49.972 IC4.4@56.957,49.972 ; 56.449,50.48 56.449,50.525 ; 56.449,50.48 56.957,50.48 ; 56.449,50.525 56.957,50.525 ; 56.449,53.229 IC4.2@56.449,53.528 ; 56.449,53.229 56.957,53.229 ; IC4.2@56.449,53.528 IC4.2@56.449,54.036 ; IC4.2@56.449,53.528 56.957,53.528 ; IC4.2@56.449,54.036 IC4.2@56.957,54.036 ; IC4.2@56.449,54.036 IC4.2@56.449,54.544 ; IC4.2@56.449,54.544 IC4.2@56.449,55.052 ; IC4.2@56.449,54.544 IC4.2@56.957,54.544 ; IC4.2@56.449,55.052 56.449,55.56 ; IC4.2@56.449,55.052 56.957,55.052 ; 56.449,55.56 56.449,55.965 ; 56.449,55.56 56.957,55.56 ; 56.449,55.965 56.957,55.961 ; 56.59,34.224 56.83,34.224 56.957,34.224 ; 56.59,34.224 56.957,34.591 ; 56.7,23.048 56.7,23.556 ; 56.7,23.048 56.957,23.048 ; 56.7,23.556 56.957,23.556 ; 56.7,23.556 56.7,24.064 ; 56.7,24.064 56.7,24.572 ; 56.7,24.064 56.957,24.064 ; 56.7,24.572 56.7,24.809 56.957,25.066 ; 56.7,24.572 56.957,24.572 ; 56.943,27.112 56.957,27.126 ; 56.957,22.372 56.957,22.54 ; 56.957,22.372 57.465,22.372 ; 56.957,22.54 56.957,23.048 ; 56.957,22.54 57.465,22.54 ; 56.957,23.048 56.957,23.556 ; 56.957,23.048 57.465,23.048 ; 56.957,23.556 56.957,24.064 ; 56.957,23.556 57.465,23.556 ; 56.957,24.064 56.957,24.572 ; 56.957,24.064 57.465,24.064 ; 56.957,24.572 56.957,25.066 ; 56.957,24.572 57.465,24.572 ; 56.957,25.066 56.971,25.08 ; 56.957,27.126 56.957,27.62 ; 56.957,27.126 57.077,27.246 ; 56.957,27.62 57.465,27.62 ; 56.957,27.62 56.957,28.128 ; 56.957,28.128 56.957,28.542 ; 56.957,28.128 57.465,28.128 ; 56.957,28.542 57.465,28.542 ; R76.1@56.957,32.596 R76.1@56.957,32.7 ; R76.1@56.957,32.596 57.367,32.596 57.367,32.7 ; R76.1@56.957,32.7 57.367,32.7 ; R76.1@56.957,32.7 R76.1@56.957,33.208 ; R76.1@56.957,33.208 57.367,33.208 ; R76.1@56.957,33.208 56.957,33.716 ; 56.957,33.716 57.367,33.716 ; 56.957,33.716 56.957,34.224 ; 56.957,34.224 57.367,34.224 ; 56.957,34.224 56.957,34.351 56.957,34.591 ; 56.957,34.591 57.005,34.638 57.465,34.638 ; 56.957,36.604 56.957,36.764 ; 56.957,36.604 57.465,36.604 ; 56.957,36.764 56.957,37.272 ; 56.957,36.764 57.465,36.764 ; 56.957,37.272 56.957,37.78 ; 56.957,37.272 57.465,37.272 ; 56.957,37.78 56.957,38.288 ; 56.957,37.78 57.465,37.78 ; 56.957,38.288 56.957,38.796 ; 56.957,38.288 57.465,38.288 ; 56.957,38.796 56.957,39.304 ; 56.957,38.796 57.465,38.796 ; 56.957,39.304 56.957,39.812 ; 56.957,39.304 57.465,39.304 ; 56.957,39.812 56.957,40.32 ; 56.957,39.812 57.465,39.812 ; 56.957,40.32 56.957,40.828 ; 56.957,40.32 57.465,40.32 ; 56.957,40.828 56.957,41.336 ; 56.957,40.828 57.465,40.828 ; 56.957,41.336 56.957,41.844 ; 56.957,41.336 57.465,41.336 ; 56.957,41.844 56.957,42.352 ; 56.957,41.844 57.465,41.844 ; 56.957,42.352 56.957,42.86 ; 56.957,42.352 57.465,42.352 ; 56.957,42.86 56.957,43.368 ; 56.957,42.86 57.465,42.86 ; 56.957,43.368 56.957,43.876 ; 56.957,43.368 57.465,43.368 ; 56.957,43.876 56.957,44.384 ; 56.957,43.876 57.465,43.876 ; 56.957,44.384 56.957,44.635 ; 56.957,44.384 57.465,44.384 ; 56.957,44.635 57.465,44.635 ; 56.957,46.838 56.957,46.924 ; 56.957,46.838 57.465,46.838 ; 56.957,46.924 56.957,47.432 ; 56.957,46.924 57.465,46.924 ; 56.957,47.432 56.957,47.94 ; 56.957,47.432 57.465,47.432 ; 56.957,47.94 IC4.4@56.957,48.448 ; 56.957,47.94 57.465,47.94 ; IC4.4@56.957,48.448 IC4.4@56.957,48.956 ; IC4.4@56.957,48.448 IC4.4@57.465,48.448 ; IC4.4@56.957,48.956 IC4.4@57.465,48.956 ; IC4.4@56.957,48.956 IC4.4@56.957,49.464 ; IC4.4@56.957,49.464 IC4.4@56.957,49.972 ; IC4.4@56.957,49.464 IC4.4@57.465,49.464 ; IC4.4@56.957,49.972 56.957,50.48 ; IC4.4@56.957,49.972 IC4.4@57.465,49.972 ; 56.957,50.48 56.957,50.525 ; 56.957,50.48 57.465,50.48 ; 56.957,50.525 57.465,50.525 ; 56.957,53.229 57.465,53.229 ; 56.957,53.229 56.957,53.528 ; 56.957,53.528 IC4.2@56.957,54.036 ; 56.957,53.528 57.465,53.528 ; IC4.2@56.957,54.036 IC4.2@56.957,54.544 ; IC4.2@56.957,54.036 57.448,54.036 ; IC4.2@56.957,54.544 56.957,55.052 ; IC4.2@56.957,54.544 57.448,54.544 ; 56.957,55.052 56.957,55.56 ; 56.957,55.052 57.465,55.052 ; 56.957,55.56 56.957,55.961 ; 56.957,55.56 57.465,55.56 ; 56.957,55.961 57.465,55.958 ; 56.971,25.08 57.465,25.08 ; 56.971,25.08 57.465,25.574 ; 57.077,27.246 cw(c57.592,26.731) 57.465,27.448 ; 57.077,27.246 cw(c57.592,26.731) 57.465,27.448 ; 57.367,32.7 57.367,33.208 ; 57.367,33.208 57.367,33.716 ; 57.367,33.716 57.367,34.224 ; 57.367,34.224 57.367,34.276 57.465,34.276 ; 57.448,54.036 cw(c58.862,54.227) 57.435,54.227 57.435,54.354 cw(c58.862,54.354) 57.448,54.544 ; 57.448,54.036 ccw(c58.862,54.227) 57.465,53.935 ; 57.448,54.544 cw(c58.862,54.354) 57.465,54.645 ; 57.465,22.372 57.973,22.372 ; 57.465,22.372 57.465,22.54 ; 57.465,22.54 57.973,22.54 ; 57.465,22.54 57.465,23.048 ; 57.465,23.048 57.973,23.048 ; 57.465,23.048 57.465,23.556 ; 57.465,23.556 57.465,24.064 ; 57.465,23.556 57.973,23.556 ; 57.465,24.064 57.465,24.572 ; 57.465,24.064 57.973,24.064 ; 57.465,24.572 57.973,24.572 ; 57.465,24.572 57.465,25.08 ; 57.465,25.08 57.973,25.08 ; 57.465,25.08 57.465,25.574 ; 57.465,25.574 57.479,25.588 ; 57.465,27.448 cw(c57.592,26.731) 57.592,27.46 ; 57.465,27.448 cw(c57.592,26.731) 57.592,27.46 ; 57.465,27.448 57.465,27.62 ; 57.465,27.62 57.465,28.128 ; 57.465,27.62 57.973,27.62 ; 57.465,28.128 57.465,28.542 ; 57.465,28.128 57.973,28.128 ; 57.465,28.542 57.973,28.542 ; 57.465,34.276 57.973,34.276 ; 57.465,34.276 57.465,34.478 57.465,34.638 ; 57.465,34.638 57.973,34.638 ; 57.465,36.604 57.465,36.764 ; 57.465,36.764 57.465,37.272 ; 57.465,36.764 57.928,36.764 ; 57.465,37.272 57.465,37.78 ; 57.465,37.272 57.928,37.272 ; 57.465,37.78 57.465,38.288 ; 57.465,37.78 57.928,37.78 ; 57.465,38.288 57.465,38.796 ; 57.465,38.288 57.928,38.288 ; 57.465,38.796 57.465,39.304 ; 57.465,38.796 57.928,38.796 ; 57.465,39.304 57.465,39.812 ; 57.465,39.304 57.928,39.304 ; 57.465,39.812 57.465,40.32 ; 57.465,39.812 57.928,39.812 ; 57.465,40.32 57.465,40.828 ; 57.465,40.32 57.928,40.32 ; 57.465,40.828 57.465,41.336 ; 57.465,40.828 57.928,40.828 ; 57.465,41.336 57.465,41.844 ; 57.465,41.336 57.848,41.336 ; 57.465,41.844 57.465,42.352 ; 57.465,41.844 57.675,41.844 ; 57.465,42.352 57.465,42.86 ; 57.465,42.352 57.786,42.352 ; 57.465,42.86 57.465,43.368 ; 57.465,42.86 57.973,42.86 ; 57.465,43.368 57.465,43.876 ; 57.465,43.368 57.973,43.368 ; 57.465,43.876 57.465,44.384 ; 57.465,43.876 57.973,43.876 ; 57.465,44.384 57.465,44.635 ; 57.465,44.384 57.973,44.384 ; 57.465,44.635 57.973,44.635 ; 57.465,46.838 57.465,46.924 ; 57.465,46.838 57.973,46.838 ; 57.465,46.924 57.465,47.432 ; 57.465,46.924 57.973,46.924 ; 57.465,47.432 57.465,47.94 ; 57.465,47.432 57.973,47.432 ; 57.465,47.94 IC4.4@57.465,48.448 ; 57.465,47.94 57.973,47.94 ; IC4.4@57.465,48.448 IC4.4@57.465,48.956 ; IC4.4@57.465,48.448 57.973,48.448 ; IC4.4@57.465,48.956 57.973,48.956 ; IC4.4@57.465,48.956 IC4.4@57.465,49.464 ; IC4.4@57.465,49.464 IC4.4@57.465,49.972 ; IC4.4@57.465,49.464 57.973,49.464 ; IC4.4@57.465,49.972 57.465,50.48 ; IC4.4@57.465,49.972 57.973,49.972 ; 57.465,50.48 57.465,50.525 ; 57.465,50.48 57.973,50.48 ; 57.465,50.525 57.973,50.525 ; 57.465,53.229 57.465,53.528 ; 57.465,53.528 57.465,53.935 ; 57.465,53.528 57.618,53.528 ; 57.465,53.935 ccw(c58.862,54.227) 57.614,53.535 ccw(c58.862,54.227) 57.618,53.528 ; 57.465,54.645 cw(c58.862,54.354) 57.614,55.045 cw(c58.862,54.354) 57.618,55.052 ; 57.465,54.645 57.465,55.052 ; 57.465,55.052 57.465,55.56 ; 57.465,55.052 57.618,55.052 ; 57.465,55.56 57.465,55.958 ; 57.465,55.56 57.973,55.56 ; 57.465,55.958 57.973,55.955 ; 57.479,25.588 57.973,25.588 ; 57.479,25.588 57.894,26.002 57.973,26.002 ; 57.592,27.46 57.973,27.46 ; 57.675,41.844 cw(c58.656,41.895) 57.786,42.352 ; 57.675,41.844 ccw(c58.656,41.895) 57.848,41.336 ; 57.786,42.352 cw(c58.656,41.895) 57.789,42.356 cw(c58.656,41.895) 57.973,42.601 57.973,42.86 ; 57.928,36.764 57.928,37.272 ; 57.928,37.272 57.928,37.78 ; 57.928,37.78 57.928,38.288 ; 57.928,38.288 57.928,38.796 ; 57.928,38.796 57.928,39.304 ; 57.928,39.304 57.928,39.812 ; 57.928,39.812 57.928,40.32 ; 57.928,40.32 57.928,40.828 ; 57.973,22.372 58.481,22.372 ; 57.973,22.372 57.973,22.54 ; 57.973,22.54 58.481,22.54 ; 57.973,22.54 57.973,23.048 ; 57.973,23.048 58.481,23.048 ; 57.973,23.048 57.973,23.556 ; 57.973,23.556 57.973,24.064 ; 57.973,23.556 58.481,23.556 ; 57.973,24.064 57.973,24.572 ; 57.973,24.064 58.481,24.064 ; 57.973,24.572 58.481,24.572 ; 57.973,24.572 57.973,25.08 ; 57.973,25.08 57.973,25.588 ; 57.973,25.08 58.481,25.08 ; 57.973,25.588 57.973,26.002 ; 57.973,25.588 58.481,25.588 ; 57.973,26.002 58.481,26.002 ; 57.973,27.46 57.973,27.62 ; 57.973,27.46 58.481,27.46 ; 57.973,27.62 57.973,28.128 ; 57.973,27.62 58.481,27.62 ; 57.973,28.128 57.973,28.542 ; 57.973,28.128 58.481,28.128 ; 57.973,28.542 58.481,28.542 ; 57.973,34.276 57.973,34.478 57.973,34.638 ; 57.973,34.276 pad.@58.481,34.276 ; 57.973,34.638 pad.@58.481,34.638 ; 57.973,42.86 57.973,43.368 ; 57.973,42.86 58.471,42.86 ; 57.973,43.368 57.973,43.876 ; 57.973,43.368 58.481,43.368 ; 57.973,43.876 57.973,44.384 ; 57.973,43.876 58.481,43.876 ; 57.973,44.384 57.973,44.635 ; 57.973,44.384 58.481,44.384 ; 57.973,44.635 58.481,44.635 ; 57.973,46.838 57.973,46.924 ; 57.973,46.838 58.481,46.838 ; 57.973,46.924 57.973,47.432 ; 57.973,46.924 58.481,46.924 ; 57.973,47.432 57.973,47.94 ; 57.973,47.432 58.481,47.432 ; 57.973,47.94 57.973,48.448 ; 57.973,47.94 58.481,47.94 ; 57.973,48.448 57.973,48.956 ; 57.973,48.448 58.481,48.448 ; 57.973,48.956 57.973,49.464 ; 57.973,48.956 58.481,48.956 ; 57.973,49.464 57.973,49.972 ; 57.973,49.464 58.481,49.464 ; 57.973,49.972 57.973,50.48 ; 57.973,49.972 58.481,49.972 ; 57.973,50.48 57.973,50.525 ; 57.973,50.48 58.481,50.48 ; 57.973,50.525 58.481,50.525 ; 57.973,55.56 57.973,55.955 ; 57.973,55.56 58.1,55.56 ; 57.973,55.955 58.481,55.951 ; 58.1,55.56 cw(c58.862,54.354) 58.344,55.683 ; 58.344,55.683 58.481,55.82 ; 58.471,42.86 cw(c58.656,41.895) 58.481,42.862 ; 58.481,22.372 58.481,22.54 ; 58.481,22.372 58.989,22.372 ; 58.481,22.54 58.481,23.048 ; 58.481,22.54 58.989,22.54 ; 58.481,23.048 58.481,23.556 ; 58.481,23.048 58.989,23.048 ; 58.481,23.556 58.481,24.064 ; 58.481,23.556 58.989,23.556 ; 58.481,24.064 58.481,24.572 ; 58.481,24.064 58.989,24.064 ; 58.481,24.572 58.481,25.08 ; 58.481,24.572 58.989,24.572 ; 58.481,25.08 58.481,25.588 ; 58.481,25.08 58.989,25.08 ; 58.481,25.588 58.481,26.002 ; 58.481,25.588 58.989,25.588 ; 58.481,26.002 58.989,26.002 ; 58.481,27.46 58.481,27.62 ; 58.481,27.46 58.989,27.46 ; 58.481,27.62 58.481,28.128 ; 58.481,27.62 58.989,27.62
